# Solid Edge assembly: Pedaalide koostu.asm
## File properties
Last saved by: Türk
Revision: 37
Application: Solid Edge
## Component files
pedaalipulk.par
Pedaalide hoidja.par
Siudr.par
Gaas.par
Sidur_pidur.par
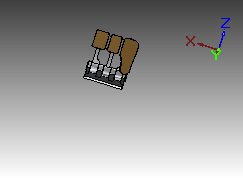
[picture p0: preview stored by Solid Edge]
